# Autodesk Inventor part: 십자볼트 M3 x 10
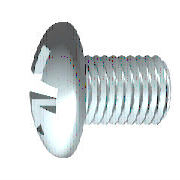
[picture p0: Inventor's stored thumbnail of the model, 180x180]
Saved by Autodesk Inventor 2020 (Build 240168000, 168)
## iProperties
Created: 2012-02
Part Number: 십자볼트 M3 x 10
Material: 스테인리스강
Description: 십자 오목 머리 나사
Document SubType Name: Modeling
Standard: KS B 1023
Designer: mduedu
Standards Organization: KS
Language: ko-KR
Size Designation: A  M 3 x 10 - H
Categories: <MemberInstance><Categories><Category DisplayName="조임쇠" InternalName="e4da775c-781d-43d5-af7c-5136215cf5a6" Mnemonic="FSTN"><Category DisplayName="볼트" InternalN
Density: 8.08 g/cm^3
Mass: 0.909379 g
Surface Area: 1.77891 cm^2
Volume: 0.112547 cm^3
Appearance: 반광택
IsCustomPart: 0
Author: mduedu
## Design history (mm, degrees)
body "Solid1"
workplane "Work Plane3"
sketch "스케치2"
  geometry: L1 (-3.72, 0)-(3.72, 0) reference; L2 (0, -3.72)-(0, 3.72) reference; L3 (0, 1.5)-(0, 0); L4 (0, 0)-(1.5, 0); L5 (0, 0)-(1.879, 1.879); L6 (0.253, 1.479)-(0.261, 0.456); L7 (1.479, 0.253)-(0.456, 0.261); L8 (0.253, -1.479)-(0.261, -0.456); L9 (1.479, -0.253)-(0.456, -0.261); L10 (-0.253, 1.479)-(-0.261, 0.456); L11 (-1.479, 0.253)-(-0.456, 0.261); L12 (-1.479, -0.253)-(-0.456, -0.261); L13 (-0.253, -1.479)-(-0.261, -0.456); A1 r 0.45 centre (0, 0) between (0.45, 0) and (0, 0.45); A2 r 1.5 centre (0, 0) between (1.5, 0) and (1.479, 0.253); A3 r 1.5 centre (0, 0) between (0.253, 1.479) and (0, 1.5); A4 r 1.5 centre (0, 0) between (1.479, 0.253) and (0.253, 1.479); A5 r 1.5 centre (0, 0) between (0, -1.5) and (0.253, -1.479); A6 r 1.5 centre (0, 0) between (0.253, -1.479) and (1.479, -0.253); A7 r 1.5 centre (0, 0) between (1.479, -0.253) and (1.5, 0); A8 r 1.5 centre (0, 0) between (-1.479, 0.253) and (-1.5, 0); A9 r 1.5 centre (0, 0) between (-0.253, 1.479) and (-1.479, 0.253); A10 r 1.5 centre (0, 0) between (0, 1.5) and (-0.253, 1.479); A11 r 1.5 centre (0, 0) between (-1.5, 0) and (-1.479, -0.253); A12 r 1.5 centre (0, 0) between (-1.479, -0.253) and (-0.253, -1.479); A13 r 1.5 centre (0, 0) between (-0.253, -1.479) and (0, -1.5); A14 r 0.525 centre (0, 0) between (0.525, 0) and (0, 0.525); A15 r 0.197 centre (0.457, 0.457) between (0.261, 0.456) and (0.456, 0.261); A16 r 0.197 centre (0.457, -0.457) between (0.456, -0.261) and (0.261, -0.456); A17 r 0.197 centre (-0.457, 0.457) between (-0.456, 0.261) and (-0.261, 0.456); A18 r 0.197 centre (-0.457, -0.457) between (-0.261, -0.456) and (-0.456, -0.261); 1 further point
  constraints: 38 point on circle, 22 end point, 19 symmetric about line, 18 centre point, 4 coincident, 3 collinear, 3 point on line, 3 tangent, 1 perpendicular, 21 other
  dimensions: "d4" = 45 deg angle of L5 L4; "d5" = 0.9 diameter of A1 (= 0.3 x SDM); "d6" = 3 diameter of A4 (= SDM); "d7" = 0.2525 distance from line of L6.start L3 (= 0.5 x SBR); "d14" = 1.05 diameter of A14 (= 0.35 x SDM)
extrude "슬롯" join sketch "스케치2" taper "d15" = 5 deg; stored distance "d54" = 10
revolve "절단부" stored, may be unused: angle "d56" = 90 deg
revolve "본체" stored, may be unused: angle "d18" = 90 deg
workplane "Work Plane1"
sketch "스케치1"
  geometry: L1 (10, 0)-(10, 1.5); L2 (10, 1.5)-(1, 1.5); L3 (3.962, 5.08)-(3.962, 5.08); L4 (-2.4, 0)-(-2.4, 2.59); L5 (-2.2, 1.4)-(-1.036, 0.82); L6 (-1.036, 0.82)-(-0.6, 0); L7 (-0.6, 0)-(10, 0); L8 (-5.105, 0)-(12.517, 0) reference; L9 (0, -1.016)-(0, 6.096) reference; L10 (-2.2, 1.4)-(-2.4, 1.5); L11 (-1.636, 2.657)-(-2.4, 2.59); L12 (-1.636, 2.657)-(0, 2.8); L13 (0, 2.8)-(0, 1.347); L14 (0, 1.347)-(0.693, 1.347); L15 (0.693, 1.347)-(1, 1.5); L16 (1, 1.5)-(0, 1.5); A1 r 5 centre (2.6, 0) between (-1.636, 2.657) and (-2.4, 0)
  constraints: 28 end point, 5 point on line, 4 collinear, 4 point on circle, 3 parallel, 2 perpendicular, 1 centre point, 1 horizontal, 1 tangent
  dimensions: "d1" = 3 diameter of L2 L7 (= GD); "d2" = 1.8 distance from line of L6.end L4 (= STI); "d11" = 3 diameter of L10.end L7 (= SDM); "d12" = 62 deg angle of L6 L7; "d13" = 26.5 deg angle of L5 L7; "d17" = 5.6 diameter of L12.end L7 (= KOD); "d19" = 5 deg angle of L12 L7 (= KEWI); "d20" = 2.4 distance between parallel lines of L4 L13 (= KOH); "d21" = 5 radius of A1 (= KR); "d23" = 2.6935 diameter of L14 L7 (= BDM); "d24" = 9 distance of L1.end L2.end (= GEL); "d25" = 0.30673 horizontal distance of L14.end L2.end (= GAL); "d28" = 10 distance between parallel lines of L1 L13 (= NLG)
fillet "모깎기1" dims "d29" = 1.2 (= RR)
fillet "모깎기2" dims "d16" = 0.101 (= 0.2 x SBR)
feature "스레드" dims "d8" = 9 (= GEL), "d9" = 0
chamfer "모따기1" distance "d26" = 0.30673 (= -0.5 x SPD + 0.5 x GD); stored, may be unused: second distance "d27" = 0.30683 (computed from GUL), angle "d78" = 45 deg
other parameters: "GD" = 3 (= NND) [user parameter; used in 2 equation terms], "NLG" = 10 [user parameter; used in 1 equation term], "GEL" = 9 [user parameter; used in 2 equation terms], "KOD" = 5.6 [user parameter; used in 1 equation term], "KOH" = 2.4 [user parameter; used in 2 equation terms], "SDM" = 3 [user parameter; used in 4 equation terms], "STI" = 1.8 [user parameter; used in 1 equation term], "SBR" = 0.505 [user parameter; used in 2 equation terms], "GAL" = 0.30673 (= 0.61345 x PTC) [user parameter; used in 1 equation term], "SPD" = 2.38655 (= NND - 1.2269 x PTC) [user parameter; used in 1 equation term], "KEWI" = 5 deg [user parameter; used in 1 equation term], "d3" = -2.4 (= -KOH), "d10" = 0, "KR" = 5 [user parameter; used in 1 equation term], "BDM" = 2.6935 [user parameter; used in 1 equation term], "GUL" = 0.30673 (= 0.61345 x PTC) [user parameter; used in 1 equation term], "RR" = 1.2 [user parameter; used in 1 equation term], "d79" = 0, "d80" = 0, "PTC" = 0.5 [user parameter; used in 5 equation terms], "THREADDIA" = 3 [user parameter; used in 1 equation term], "TOA" = 30 deg [user parameter], "NND" = 3 [user parameter; used in 2 equation terms], "GD1" = 2.38655 (= THREADDIA - 1.2269 x PTC) [user parameter]
